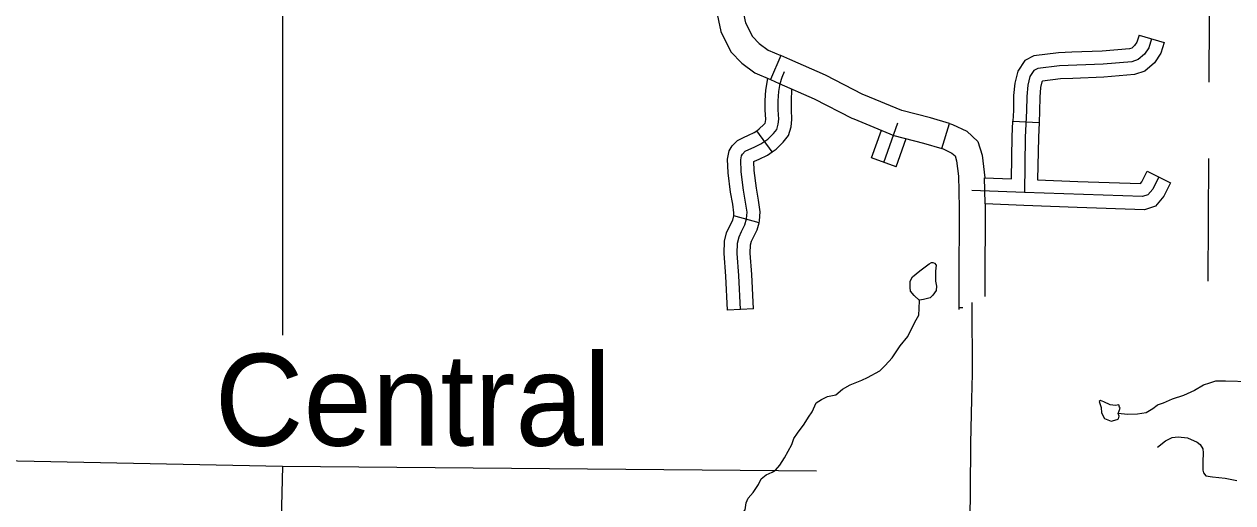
# Model space of a CAD drawing. Extents: x 813775 to 1157140, y 1757555 to 1979907.
# Drawn here: x 951173 to 965049, y 1832939 to 1838441 of the extents above; entities that cross this region are included whole.
import ezdxf

# ---------------------------------------------------------------- set-up
doc = ezdxf.new("R2010")
doc.units = 0
for name, color, linetype in [('Level 24', 7, 'Continuous'), ('Level 31', 7, 'Continuous'), ('Level 32', 7, 'Continuous'), ('Level 35', 7, 'Continuous'), ('Level 5', 7, 'Continuous')]:
    doc.layers.add(name, color=color, linetype=linetype)

msp = doc.modelspace()

# ---------------------------------------------------------------- linework, layer by layer
at = {"layer": 'Level 31'}
for p, q in [((963973, 1838316), (964260, 1838229)), ((959860, 1838079), (959740, 1837804)), ((960811, 1837629), (960811, 1837629)), ((961710, 1837011), (961796, 1837298)), ((962525, 1837324), (962825, 1837311)), ((964066, 1836752), (964335, 1836619)), ((962207, 1836374), (962206, 1836374)), ((961904, 1835186), (961949, 1835186))]:
    msp.add_line(p, q, dxfattribs=at)
for points in [[(959108, 1838751), (959116, 1838609), (959171, 1838357), (959287, 1838124), (959414, 1837992), (959562, 1837881), (959740, 1837804)], [(959408, 1838768), (959414, 1838650), (959456, 1838458), (959535, 1838299), (959613, 1838218), (959714, 1838142), (959860, 1838079)], [(963973, 1838316), (963948, 1838234), (963922, 1838195), (963888, 1838166), (963861, 1838157), (963550, 1838132), (963199, 1838118)], [(964260, 1838229), (964223, 1838107), (964150, 1837995), (964038, 1837899), (963920, 1837861), (963568, 1837832), (963211, 1837818)], [(964116, 1838272), (964085, 1838170), (964036, 1838095), (963963, 1838033), (963890, 1838009)], [(960811, 1837629), (960802, 1837632), (960373, 1837854), (959963, 1838034), (959860, 1838079)], [(963199, 1838118), (963048, 1838112), (962766, 1838076), (962663, 1838022), (962579, 1837902), (962545, 1837762), (962533, 1837619), (962530, 1837450), (962525, 1837324)], [(963890, 1838009), (963559, 1837982), (963060, 1837962), (962811, 1837931), (962765, 1837907), (962718, 1837840), (962694, 1837738), (962683, 1837611), (962680, 1837445), (962667, 1837143), (962656, 1836505)], [(959740, 1837804), (959842, 1837759), (960244, 1837583), (960676, 1837360), (960697, 1837351)], [(963211, 1837818), (963072, 1837812), (962864, 1837786), (962857, 1837777), (962842, 1837714), (962832, 1837603), (962830, 1837441), (962825, 1837311)], [(961796, 1837298), (961578, 1837363), (961251, 1837448), (960811, 1837629)], [(960697, 1837351), (961156, 1837163), (961497, 1837074), (961710, 1837011)], [(961796, 1837298), (961831, 1837288), (961996, 1837211), (962121, 1837093), (962173, 1836935), (962202, 1836674)], [(962509, 1836662), (962517, 1837148), (962525, 1837324)], [(962825, 1837311), (962817, 1837139), (962808, 1836650)], [(961710, 1837011), (961724, 1837007), (961825, 1836959), (961860, 1836926), (961878, 1836870), (961898, 1836693), (961902, 1836526), (961907, 1836319), (961906, 1836244)], [(962206, 1836374), (962202, 1836533), (962199, 1836674)], [(962199, 1836674), (962509, 1836662)], [(963271, 1836634), (963989, 1836610), (964006, 1836629), (964066, 1836752)], [(964201, 1836685), (964132, 1836545), (964074, 1836479), (964014, 1836459)], [(964014, 1836459), (962656, 1836505), (962052, 1836530)], [(962808, 1836650), (963271, 1836634)], [(964335, 1836619), (964258, 1836462), (964161, 1836350), (964036, 1836308), (963261, 1836335)], [(961906, 1836244), (961902, 1835534), (961904, 1835162)], [(962206, 1836242), (962202, 1835534), (962203, 1835312)], [(962207, 1836374), (962206, 1836242)], [(963261, 1836335), (962650, 1836356), (962207, 1836374)], [(962054, 1835241), (962057, 1834421), (962050, 1834131)], [(962050, 1834131), (962039, 1833621), (962033, 1833075)], [(964183, 1833579), (964276, 1833653), (964352, 1833691), (964420, 1833699), (964527, 1833686), (964640, 1833637), (964676, 1833611), (964705, 1833559), (964707, 1833515), (964705, 1833411), (964705, 1833313), (964713, 1833282), (964740, 1833251), (964816, 1833237), (964960, 1833222), (965095, 1833197)], [(962033, 1833075), (962021, 1832151), (962022, 1832019)]]:
    msp.add_lwpolyline(points, dxfattribs=at)
at = {"layer": 'Level 32'}
for p, q in [((959760, 1836972), (959585, 1837216)), ((961183, 1836802), (960900, 1836903)), ((959610, 1836156), (959321, 1836237)), ((959546, 1835168), (959246, 1835155))]:
    msp.add_line(p, q, dxfattribs=at)
for points in [[(959456, 1836393), (959432, 1836531), (959405, 1836745), (959399, 1836880), (959407, 1836929), (959419, 1836947), (959452, 1836980), (959494, 1837002), (959552, 1837027), (959632, 1837065), (959709, 1837120), (959776, 1837185), (959814, 1837232), (959831, 1837290), (959836, 1837348), (959831, 1837457), (959831, 1837559), (959836, 1837665), (959851, 1837757), (959874, 1837830), (959903, 1837897)], [(959585, 1837216), (959613, 1837236), (959665, 1837286), (959679, 1837303), (959683, 1837318), (959686, 1837350), (959681, 1837453), (959681, 1837562), (959686, 1837681), (959710, 1837817)], [(959760, 1836972), (959806, 1837005), (959887, 1837084), (959949, 1837161), (959980, 1837262), (959986, 1837345), (959981, 1837460), (959981, 1837556), (959987, 1837695)], [(959319, 1836229), (959321, 1836274), (959308, 1836370), (959283, 1836509), (959256, 1836732), (959248, 1836890), (959265, 1836984), (959300, 1837041), (959362, 1837102), (959430, 1837138), (959490, 1837164), (959555, 1837194), (959585, 1837216)], [(960900, 1836903), (961014, 1837221)], [(961041, 1836852), (961204, 1837305)], [(961183, 1836802), (961299, 1837126)], [(959610, 1836156), (959616, 1836179), (959622, 1836285), (959605, 1836417), (959580, 1836554), (959555, 1836758), (959550, 1836862), (959558, 1836867), (959613, 1836890), (959708, 1836935), (959760, 1836972)], [(959396, 1835162), (959379, 1835553), (959359, 1835806), (959363, 1835924), (959381, 1835995), (959410, 1836059), (959447, 1836133), (959467, 1836204), (959472, 1836279), (959456, 1836393)], [(959246, 1835155), (959229, 1835543), (959208, 1835803), (959214, 1835945), (959238, 1836044), (959274, 1836124), (959307, 1836188), (959321, 1836237)], [(959546, 1835168), (959528, 1835562), (959509, 1835809), (959512, 1835903), (959523, 1835946), (959545, 1835994), (959588, 1836077), (959610, 1836156)]]:
    msp.add_lwpolyline(points, dxfattribs=at)
at = {"layer": 'Level 35'}
for points in [[(961452, 1835265), (961389, 1835322), (961348, 1835371), (961343, 1835414), (961343, 1835488), (961370, 1835537), (961457, 1835607), (961563, 1835686), (961588, 1835700), (961604, 1835703), (961626, 1835694), (961642, 1835670), (961634, 1835602), (961636, 1835485), (961647, 1835428), (961642, 1835379), (961604, 1835325), (961574, 1835295), (961498, 1835278), (961452, 1835267)], [(960218, 1833986), (960264, 1834090), (960327, 1834128), (960397, 1834160), (960492, 1834182), (960568, 1834245), (960655, 1834296), (960789, 1834348), (960856, 1834381), (960995, 1834457), (961058, 1834519), (961139, 1834606), (961229, 1834745), (961318, 1834851), (961400, 1835017), (961446, 1835096), (961449, 1835172), (961452, 1835265)], [(964964, 1834337), (964850, 1834336), (964769, 1834312), (964722, 1834295), (964714, 1834293), (964608, 1834230), (964481, 1834173), (964353, 1834129), (964250, 1834083), (964193, 1834064), (964179, 1834056), (964130, 1834018), (964054, 1833972), (963953, 1833958)], [(966456, 1834300), (966241, 1834266), (966007, 1834262), (965867, 1834280), (965510, 1834307), (965246, 1834330), (964964, 1834337)], [(963731, 1833964), (963755, 1834029), (963750, 1834040), (963739, 1834064), (963701, 1834059), (963641, 1834067), (963570, 1834100), (963529, 1834116), (963516, 1834102), (963538, 1834034), (963540, 1833974), (963576, 1833909), (963654, 1833877), (963720, 1833896), (963736, 1833904), (963744, 1833936), (963731, 1833964)], [(959200, 1832508), (959216, 1832607), (959226, 1832639), (959245, 1832678), (959303, 1832727), (959346, 1832762), (959406, 1832800), (959449, 1832860), (959463, 1832939), (959485, 1832993), (959542, 1833056), (959604, 1833148), (959634, 1833213), (959691, 1833260), (959762, 1833292), (959797, 1833314), (959849, 1833371), (959903, 1833456), (959985, 1833608), (960009, 1833679), (960050, 1833738), (960126, 1833842), (960178, 1833923), (960218, 1833986)], [(963953, 1833958), (963839, 1833953), (963731, 1833964)]]:
    msp.add_lwpolyline(points, dxfattribs=at)
at = {"layer": 'Level 5'}
for points in [[(954144, 1843988), (954138, 1834867)], [(964805, 1843748), (964773, 1837775)], [(964768, 1836897), (964761, 1835488)], [(943494, 1833574), (954137, 1833359)], [(954137, 1833359), (954084, 1831203)], [(954137, 1833359), (960268, 1833306)]]:
    msp.add_lwpolyline(points, dxfattribs=at)

# ---------------------------------------------------------------- texts
at = {"layer": 'Level 24'}
msp.add_text('Central', height=1056, dxfattribs=at).set_placement((953360, 1833596))

doc.saveas('drawing.dxf')
